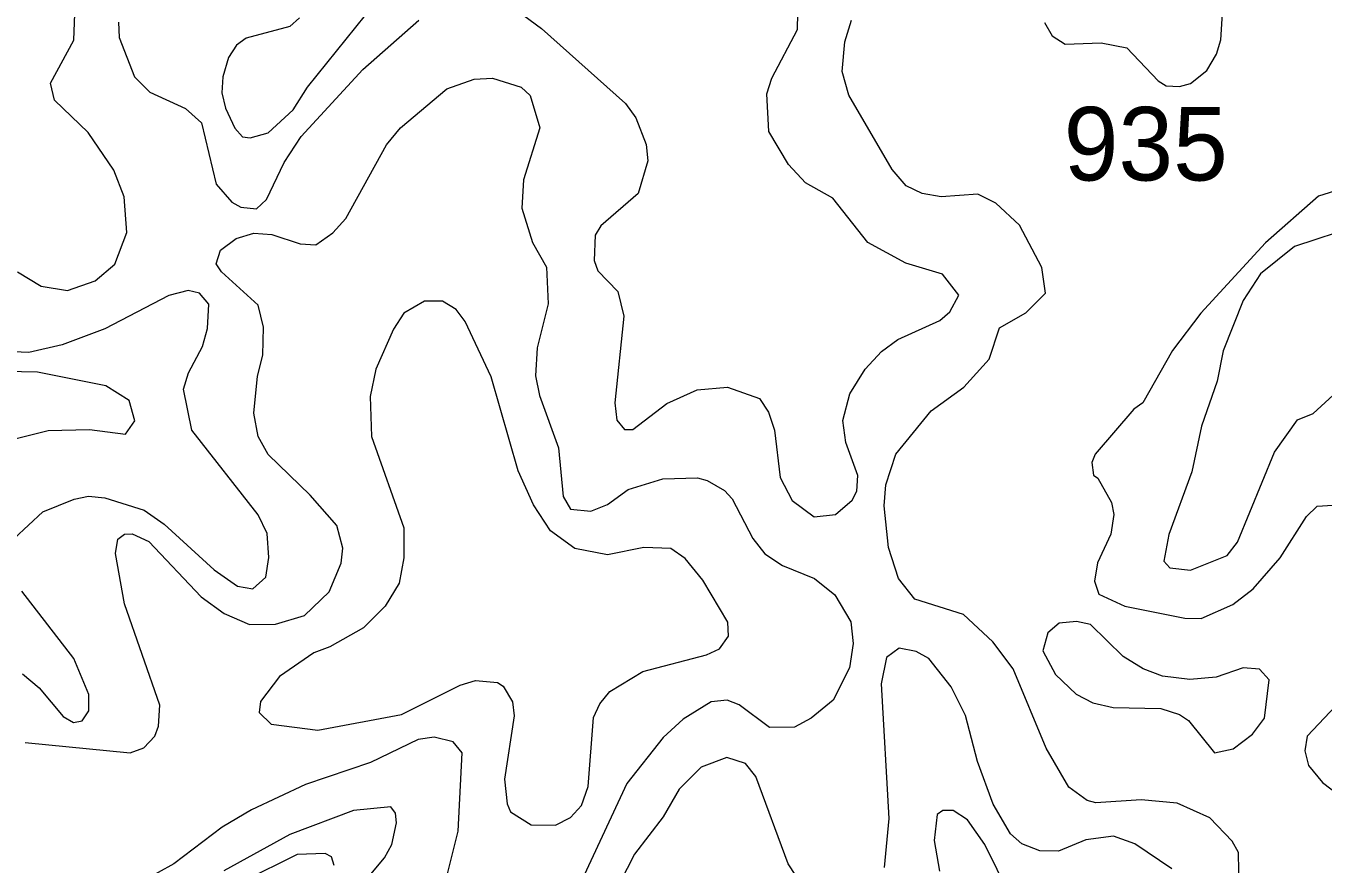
# Model space of a CAD drawing. Extents: x 763.2 to 816.8, y 7896.5 to 7952.7.
# Drawn here: x 769.081 to 771.903, y 7931.022 to 7932.845 of the extents above; entities that cross this region are included whole.
import ezdxf

# ---------------------------------------------------------------- set-up
doc = ezdxf.new("R2010")
doc.units = 0
doc.header["$LTSCALE"] = 0.064
doc.layers.add('2', color=7, linetype='Continuous', lineweight=13)
doc.layers.add('21', color=7, linetype='Continuous')

msp = doc.modelspace()

# ---------------------------------------------------------------- linework, layer by layer
at = {"layer": '2'}
for points in [[(769.0622, 7932.3099), (769.1134, 7932.279), (769.1712, 7932.2694), (769.231, 7932.2908), (769.2737, 7932.3269), (769.2998, 7932.3953), (769.2947, 7932.4729), (769.2717, 7932.5312), (769.2157, 7932.6133), (769.143, 7932.6837), (769.1343, 7932.7207), (769.185, 7932.814), (769.1867, 7932.8711), (769.1687, 7932.9283), (769.1865, 7932.9994), (769.1802, 7933.0559), (769.1504, 7933.1354), (769.0994, 7933.2026), (769.0764, 7933.2125)], [(769.6757, 7932.8624), (769.6548, 7932.8434), (769.5598, 7932.8183), (769.5386, 7932.8032), (769.5217, 7932.7763), (769.5088, 7932.7344), (769.5072, 7932.699), (769.5147, 7932.6663), (769.5351, 7932.6228), (769.5517, 7932.6033), (769.5686, 7932.6015), (769.6075, 7932.6123), (769.6622, 7932.6626), (769.6933, 7932.712), (769.8824, 7932.947)], [(770.1365, 7932.8879), (770.2022, 7932.8396), (770.3855, 7932.6762), (770.4081, 7932.6449), (770.4305, 7932.5872), (770.4336, 7932.5515), (770.4126, 7932.4804), (770.3314, 7932.4101), (770.319, 7932.39), (770.3172, 7932.3349), (770.3249, 7932.3121), (770.3683, 7932.267), (770.3815, 7932.2137), (770.3618, 7932.0252), (770.3667, 7931.9877), (770.3832, 7931.9674), (770.401, 7931.9672), (770.4755, 7932.024), (770.5412, 7932.0535), (770.6076, 7932.0589), (770.6769, 7932.0342), (770.6967, 7932.0048), (770.7099, 7931.966), (770.7218, 7931.8628), (770.7479, 7931.8124), (770.7957, 7931.7772), (770.8425, 7931.7819), (770.8784, 7931.8131), (770.8886, 7931.8327), (770.8909, 7931.867), (770.8647, 7931.9391), (770.8582, 7931.987), (770.8732, 7932.0448), (770.9071, 7932.0987), (770.9424, 7932.1367), (770.9778, 7932.1632), (771.0696, 7932.2045), (771.0914, 7932.2234), (771.1105, 7932.2595), (771.0751, 7932.3047), (770.9952, 7932.3292), (770.9125, 7932.374), (770.8365, 7932.47), (770.7774, 7932.5035), (770.74, 7932.5433), (770.6976, 7932.6155), (770.6928, 7932.6972), (770.7036, 7932.7311), (770.76, 7932.8372), (770.7609, 7932.9086)], [(771.297, 7932.8521), (771.3135, 7932.8233), (771.3422, 7932.8054), (771.4207, 7932.8082), (771.4764, 7932.7973), (771.5445, 7932.7252), (771.562, 7932.7145), (771.5913, 7932.7131), (771.6146, 7932.7199), (771.6505, 7932.7482), (771.6712, 7932.7831), (771.6808, 7932.8145), (771.6849, 7932.8837)], [(769.2821, 7932.8531), (769.2837, 7932.8199), (769.3167, 7932.7345), (769.3505, 7932.7006), (769.4281, 7932.6655), (769.4623, 7932.6339), (769.4944, 7932.5005), (769.5286, 7932.4619), (769.5483, 7932.4504), (769.5821, 7932.4471), (769.6042, 7932.467), (769.6424, 7932.5477), (769.6797, 7932.6045), (769.8139, 7932.7503), (769.9355, 7932.8572)], [(771.7208, 7930.9661), (771.7193, 7931.0469), (771.7054, 7931.0716), (771.6567, 7931.1222), (771.5859, 7931.1545), (771.5077, 7931.1617), (771.4088, 7931.1554), (771.39, 7931.1605), (771.3502, 7931.1894), (771.3008, 7931.2737), (771.229, 7931.4466), (771.185, 7931.5051), (771.1212, 7931.565), (771.0153, 7931.5984), (770.9793, 7931.6431), (770.958, 7931.7104), (770.9485, 7931.801), (770.9518, 7931.847), (770.9735, 7931.9137), (771.0504, 7932.0079), (771.1215, 7932.0594), (771.1767, 7932.1199), (771.1992, 7932.188), (771.2569, 7932.2209), (771.2996, 7932.2634), (771.2917, 7932.3197), (771.2429, 7932.4117), (771.1914, 7932.4592), (771.1519, 7932.4792), (771.0724, 7932.4732), (771.0309, 7932.4803), (770.9958, 7932.4971), (770.9653, 7932.5326), (770.8714, 7932.6944), (770.8565, 7932.7457), (770.863, 7932.81), (770.8773, 7932.8572)], [(769.0792, 7931.2865), (769.3073, 7931.2638), (769.3372, 7931.2748), (769.3609, 7931.3004), (769.369, 7931.3219), (769.3723, 7931.3676), (769.2954, 7931.5882), (769.2755, 7931.6973), (769.2807, 7931.7284), (769.2952, 7931.7398), (769.3121, 7931.7402), (769.348, 7931.7232), (769.4617, 7931.603), (769.5118, 7931.5669), (769.567, 7931.543), (769.6238, 7931.5437), (769.6867, 7931.5623), (769.7407, 7931.6143), (769.7669, 7931.6767), (769.7699, 7931.7089), (769.7568, 7931.758), (769.6994, 7931.824), (769.6074, 7931.9126), (769.5861, 7931.9522), (769.5763, 7932.0028), (769.5843, 7932.0829), (769.5958, 7932.1289), (769.5973, 7932.1895), (769.5858, 7932.2379), (769.506, 7932.31), (769.4948, 7932.3273), (769.5042, 7932.3568), (769.5384, 7932.3826), (769.5768, 7932.3942), (769.6156, 7932.3909), (769.677, 7932.3708), (769.7115, 7932.3686), (769.7486, 7932.3946), (769.7768, 7932.4263), (769.8654, 7932.5865), (769.8956, 7932.6232), (769.9964, 7932.7077), (770.0561, 7932.7294), (770.0962, 7932.7309), (770.1583, 7932.7118), (770.178, 7932.6936), (770.1991, 7932.6229), (770.1634, 7932.5099), (770.1597, 7932.4486), (770.1829, 7932.3739), (770.2137, 7932.3203), (770.2169, 7932.2408), (770.1928, 7932.1451)], [(771.9512, 7932.4926), (771.8935, 7932.4746), (771.7784, 7932.3728), (771.6371, 7932.22), (771.5759, 7932.139), (771.5108, 7932.0253), (771.4914, 7932.0116), (771.4074, 7931.9133), (771.4005, 7931.8956), (771.4035, 7931.868), (771.4129, 7931.861), (771.4427, 7931.8081), (771.4481, 7931.782), (771.4416, 7931.7392), (771.4128, 7931.6771), (771.4057, 7931.6376), (771.4152, 7931.609), (771.4721, 7931.5826), (771.6025, 7931.5568), (771.6379, 7931.5563), (771.7073, 7931.5863), (771.7509, 7931.6206), (771.8098, 7931.688), (771.8672, 7931.7779), (771.8904, 7931.8007), (771.9244, 7931.8024)], [(771.9784, 7932.4104), (771.8415, 7932.3648), (771.7669, 7932.3055), (771.7298, 7932.2477), (771.6859, 7932.1382), (771.6726, 7932.0725), (771.6386, 7931.9745), (771.6177, 7931.8747), (771.5674, 7931.7386), (771.5566, 7931.6807), (771.5701, 7931.6665), (771.6149, 7931.6613), (771.6945, 7931.6928), (771.7175, 7931.7222)], [(769.055, 7931.7299), (769.1177, 7931.7877), (769.1857, 7931.8159), (769.2167, 7931.8221), (769.2521, 7931.8188), (769.3376, 7931.7919), (769.3811, 7931.7611), (769.4902, 7931.6617), (769.5407, 7931.6266), (769.5743, 7931.6205), (769.6025, 7931.6456), (769.609, 7931.6886), (769.6057, 7931.7408), (769.5859, 7931.7812), (769.4413, 7931.966), (769.4236, 7932.0548), (769.4345, 7932.0906), (769.4649, 7932.1475), (769.476, 7932.187), (769.4789, 7932.2396), (769.4582, 7932.2638), (769.4333, 7932.2691), (769.3912, 7932.2587), (769.2521, 7932.1862), (769.1594, 7932.1513), (769.0872, 7932.1343), (769.0027, 7932.138)], [(770.1928, 7932.1451), (770.1892, 7932.0837), (770.1984, 7932.0408), (770.2398, 7931.9272), (770.2499, 7931.8215), (770.2653, 7931.794)], [(771.7175, 7931.7222), (771.7974, 7931.9181), (771.848, 7931.9879), (771.8816, 7932.0017), (772.0129, 7932.1226), (772.0467, 7932.1437)], [(769.0358, 7931.9415), (769.1291, 7931.9653), (769.2186, 7931.9669), (769.297, 7931.9571), (769.3179, 7931.9861), (769.3055, 7932.0302), (769.2541, 7932.0622), (769.1054, 7932.0918), (768.9319, 7932.0952)], [(770.2653, 7931.794), (770.3101, 7931.7896), (770.3464, 7931.8042), (770.391, 7931.8367), (770.4669, 7931.8598), (770.5418, 7931.8617), (770.5628, 7931.8565), (770.601, 7931.8342), (770.6178, 7931.8161), (770.6622, 7931.7298), (770.6883, 7931.6964), (770.7273, 7931.6713), (770.7968, 7931.6428), (770.8411, 7931.6072), (770.8758, 7931.5486), (770.8811, 7931.5016), (770.8726, 7931.4486), (770.8372, 7931.3782), (770.7895, 7931.3396), (770.7528, 7931.3196), (770.6987, 7931.3188), (770.6327, 7931.3686), (770.6068, 7931.3785), (770.5719, 7931.3749), (770.5107, 7931.3371), (770.4674, 7931.2969), (770.3883, 7931.1973), (770.2952, 7930.998)], [(769.0732, 7931.436), (769.1092, 7931.4051), (769.1616, 7931.3431), (769.1842, 7931.3296), (769.2033, 7931.3335), (769.2178, 7931.3554), (769.2178, 7931.3908), (769.1849, 7931.469), (769.0719, 7931.6158)], [(771.5741, 7931.0119), (771.494, 7931.0663), (771.4471, 7931.0825), (771.3874, 7931.0746), (771.3273, 7931.05), (771.2867, 7931.0504), (771.2479, 7931.066), (771.2233, 7931.0878), (771.1853, 7931.152), (771.1516, 7931.2453), (771.125, 7931.3452), (771.094, 7931.4074), (771.0453, 7931.4688), (771.0182, 7931.4846), (770.981, 7931.4917), (770.9533, 7931.4714), (770.9416, 7931.4141), (770.9582, 7931.1213), (770.9482, 7931.0148)], [(771.9433, 7931.3792), (771.8687, 7931.3004), (771.8639, 7931.2685), (771.872, 7931.236), (771.9021, 7931.199), (771.9564, 7931.158)], [(769.9975, 7930.9979), (770.0214, 7931.0937), (770.0298, 7931.2641), (770.0105, 7931.2876), (769.9687, 7931.2979), (769.9344, 7931.293), (769.8301, 7931.2431), (769.6892, 7931.1951), (769.5717, 7931.1396), (769.5075, 7931.102), (769.4025, 7931.0223), (769.3002, 7930.9661)], [(770.7713, 7930.9741), (770.7394, 7931.0227), (770.6689, 7931.2125), (770.6468, 7931.2408), (770.6059, 7931.2537), (770.5498, 7931.2326), (770.5019, 7931.1851), (770.4673, 7931.1244), (770.4052, 7931.0435), (770.3563, 7930.9482)], [(769.787, 7930.947), (769.8611, 7931.0355), (769.8769, 7931.0647), (769.8867, 7931.1114), (769.8849, 7931.1327), (769.8744, 7931.1467), (769.7931, 7931.1386), (769.6551, 7931.0859), (769.5114, 7931.0074)], [(771.2472, 7930.9026), (771.167, 7931.0647), (771.1295, 7931.1184), (771.0984, 7931.1382), (771.076, 7931.1385), (771.0638, 7931.1301), (771.0569, 7931.073), (771.0683, 7931.0062)], [(769.7515, 7931.019), (769.7452, 7931.038), (769.732, 7931.0446), (769.6711, 7931.0431), (769.5544, 7930.9849)]]:
    msp.add_lwpolyline(points, dxfattribs=at)
for points in [[(770.2332, 7931.1062), (770.2654, 7931.1229), (770.2897, 7931.1494), (770.3042, 7931.1903), (770.3158, 7931.3408), (770.3295, 7931.3703), (770.3514, 7931.3976), (770.4228, 7931.4405), (770.5616, 7931.4771), (770.5902, 7931.4901), (770.6093, 7931.5177), (770.6082, 7931.5483), (770.5534, 7931.6395), (770.5152, 7931.6869), (770.4837, 7931.7085), (770.4249, 7931.7105), (770.3459, 7931.6942), (770.2748, 7931.7084), (770.2221, 7931.7468), (770.1849, 7931.803), (770.1516, 7931.8774), (770.0929, 7932.0815), (770.0363, 7932.2019), (770.0165, 7932.2282), (769.9871, 7932.2463), (769.9477, 7932.2463), (769.9032, 7932.2199), (769.8804, 7932.1855), (769.842, 7932.0987), (769.8296, 7932.0387), (769.8327, 7931.9516), (769.9032, 7931.7534), (769.9031, 7931.6879), (769.893, 7931.6327), (769.862, 7931.5826), (769.8155, 7931.536), (769.7417, 7931.4943), (769.7071, 7931.4817), (769.6326, 7931.4301), (769.5912, 7931.3756), (769.5878, 7931.3514), (769.6139, 7931.3259), (769.7161, 7931.3132), (769.8977, 7931.3473), (770.0258, 7931.4111), (770.0587, 7931.421), (770.1065, 7931.4171), (770.1192, 7931.4089), (770.1395, 7931.3749), (770.1431, 7931.3441), (770.1218, 7931.2067), (770.1276, 7931.153), (770.1349, 7931.1359), (770.1802, 7931.1072)], [(771.7495, 7931.3044), (771.776, 7931.3395), (771.7864, 7931.4223), (771.765, 7931.4456), (771.7297, 7931.4491), (771.6706, 7931.4283), (771.6131, 7931.4231), (771.5539, 7931.4307), (771.5116, 7931.4463), (771.4687, 7931.4735), (771.3974, 7931.5431), (771.3669, 7931.5495), (771.329, 7931.5462), (771.3041, 7931.5247), (771.2938, 7931.4857), (771.3211, 7931.4342), (771.3663, 7931.3912), (771.4021, 7931.3727), (771.4464, 7931.3622), (771.5502, 7931.3606), (771.5909, 7931.3473), (771.6107, 7931.3341), (771.6674, 7931.2638), (771.7074, 7931.2724)]]:
    msp.add_lwpolyline(points, close=True, dxfattribs=at)

# ---------------------------------------------------------------- texts
at = {"layer": '21'}
msp.add_text('935', height=0.16, dxfattribs=at).set_placement((771.3391, 7932.5087))

doc.saveas('drawing.dxf')
